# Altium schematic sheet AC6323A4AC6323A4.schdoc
size 127 x 101 mm
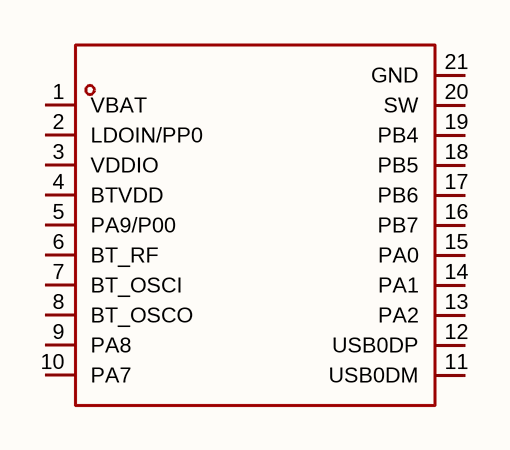
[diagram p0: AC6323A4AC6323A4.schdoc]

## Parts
U?  ac6323a4  [QFN-20_L3.0-W3.0-P0.40-TL-EP1.7]  (value not drawn)

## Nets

Not connected (* = marked no-connect by the designer): U? 1(VBAT) 2(LDOIN/PP0) 3(VDDIO) 4(BTVDD) 5(PA9/P00) 6(BT_RF) 7(BT_OSCI) 8(BT_OSCO) 9(PA8) 10(PA7) 11(USB0DM) 12(USB0DP) 13(PA2) 14(PA1) 15(PA0) 16(PB7) 17(PB6) 18(PB5) 19(PB4) 20(SW) 21(GND)

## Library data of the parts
U? = ac6323a4: CPU内核:RISC;CPU最大主频:96MHz;CPU位数:32 Bit;; Manufacturer: JL(杰理); AddInBom: yes; ModelId: a10c7af637884cc79acdab0a4df4305c; ModelName: QFN-20_L3.0-W3.0-H0.6-P0.40-BL; ModelTransform: 118.11,118.11,0,0,0,0,0,0,0; CPU Core: RISC; CPU Maximum Speed: 96MHz; Core Size: 32 Bit; Number of I/O: 17; ADC (Bit): 10bit; Voltage - Supply: 1.8V~4.5V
